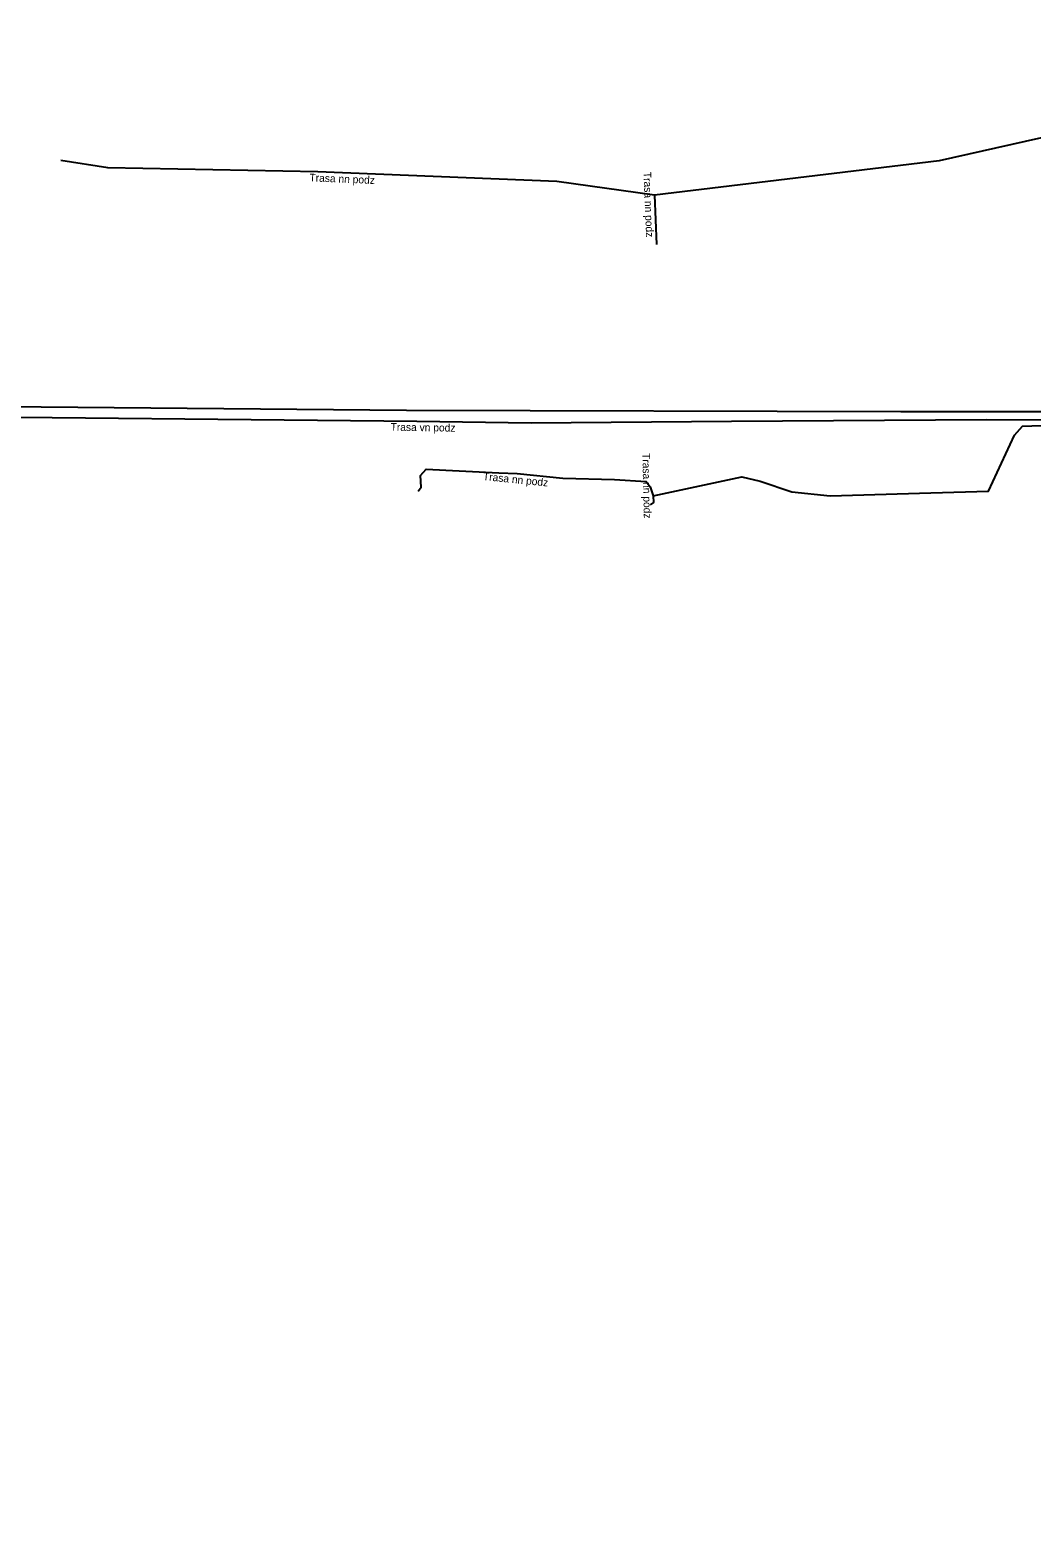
# Model space of a CAD drawing. Extents: x -756855 to -756032, y -1046964 to -1046550.
# Drawn here: x -756303.4 to -756238, y -1046658.8 to -1046560.4 of the extents above; entities that cross this region are included whole.
import ezdxf

# ---------------------------------------------------------------- set-up
doc = ezdxf.new("R2010")
doc.units = 0
for name, color, linetype in [('Popiskový text - Ostatní atributy Trasy', 7, 'Continuous'), ('Spojnice NN', 7, 'Continuous'), ('Spojnice VN', 7, 'Continuous')]:
    doc.layers.add(name, color=color, linetype=linetype)

msp = doc.modelspace()

# ---------------------------------------------------------------- linework, layer by layer
at = {"layer": 'Spojnice NN'}
for points in [[(-756196.4, -1046566.77), (-756193.9, -1046566.64), (-756194.22, -1046561.49), (-756202.37, -1046560.43), (-756217.11, -1046560.37), (-756221.91, -1046563.32), (-756226.16, -1046564.88), (-756244.08, -1046568.9), (-756262.67, -1046571.14)], [(-756262.67, -1046571.14), (-756269.04, -1046570.25), (-756284.64, -1046569.61), (-756298.35, -1046569.36), (-756301.41, -1046568.87)], [(-756262.67, -1046571.14), (-756262.54, -1046574.36)], [(-756262.74, -1046590.77), (-756262.15, -1046590.65), (-756256.97, -1046589.53), (-756255.77, -1046589.82), (-756253.69, -1046590.52), (-756251.19, -1046590.78), (-756244.63, -1046590.57), (-756240.86, -1046590.47), (-756239.16, -1046586.81), (-756238.63, -1046586.22), (-756233.69, -1046586.04)], [(-756278.09, -1046590.47), (-756277.9, -1046590.21), (-756277.95, -1046589.44), (-756277.57, -1046589.03), (-756272.83, -1046589.28), (-756271.62, -1046589.31), (-756268.65, -1046589.61), (-756265.28, -1046589.7), (-756263.2, -1046589.83), (-756262.94, -1046590.19), (-756262.74, -1046590.77)], [(-756262.74, -1046590.77), (-756262.73, -1046591.2), (-756262.94, -1046591.36)]]:
    msp.add_lwpolyline(points, dxfattribs=at)
at = {"layer": 'Spojnice VN'}
for points in [[(-756223.24, -1046585.74), (-756223.44, -1046585.74), (-756234.854, -1046585.278), (-756246.587, -1046585.278), (-756278.85, -1046585.193), (-756331.347, -1046584.718), (-756344.208, -1046585.283), (-756345.966, -1046585.847), (-756346.53, -1046586.525), (-756345.564, -1046591.094), (-756351.445, -1046592.308), (-756351.607, -1046591.493), (-756362.775, -1046591.832), (-756379.431, -1046592.061), (-756389.359, -1046591.609), (-756390.262, -1046591.722), (-756403.799, -1046596.238), (-756407.605, -1046585.018), (-756412.541, -1046587.418), (-756413.242, -1046585.898)], [(-756312.823, -1046585.557), (-756278.17, -1046585.896), (-756270.719, -1046586.007), (-756257.632, -1046585.894), (-756240.991, -1046585.781), (-756232.454, -1046585.837), (-756212.316, -1046586.628), (-756211.639, -1046587.136), (-756209.891, -1046588.604), (-756204.937, -1046614.837), (-756199.589, -1046640.057), (-756195.866, -1046658.801), (-756184.26, -1046655.924), (-756180.638, -1046655.313)]]:
    msp.add_lwpolyline(points, dxfattribs=at)

# ---------------------------------------------------------------- texts
at = {"layer": 'Popiskový text - Ostatní atributy Trasy'}
for s, rotation, p in [('Trasa nn podz', 357.65072, (-756285.197, -1046570.238)), ('Trasa nn podz', 272.31193, (-756263.382, -1046569.631)), ('Trasa vn podz', 359.14651, (-756279.896, -1046586.52)), ('Trasa nn podz', 271.33222, (-756263.455, -1046587.985)), ('Trasa nn podz', 354.23211, (-756273.878, -1046589.735))]:
    msp.add_text(s, height=0.5, rotation=rotation, dxfattribs=at).set_placement(p)

doc.saveas('drawing.dxf')
